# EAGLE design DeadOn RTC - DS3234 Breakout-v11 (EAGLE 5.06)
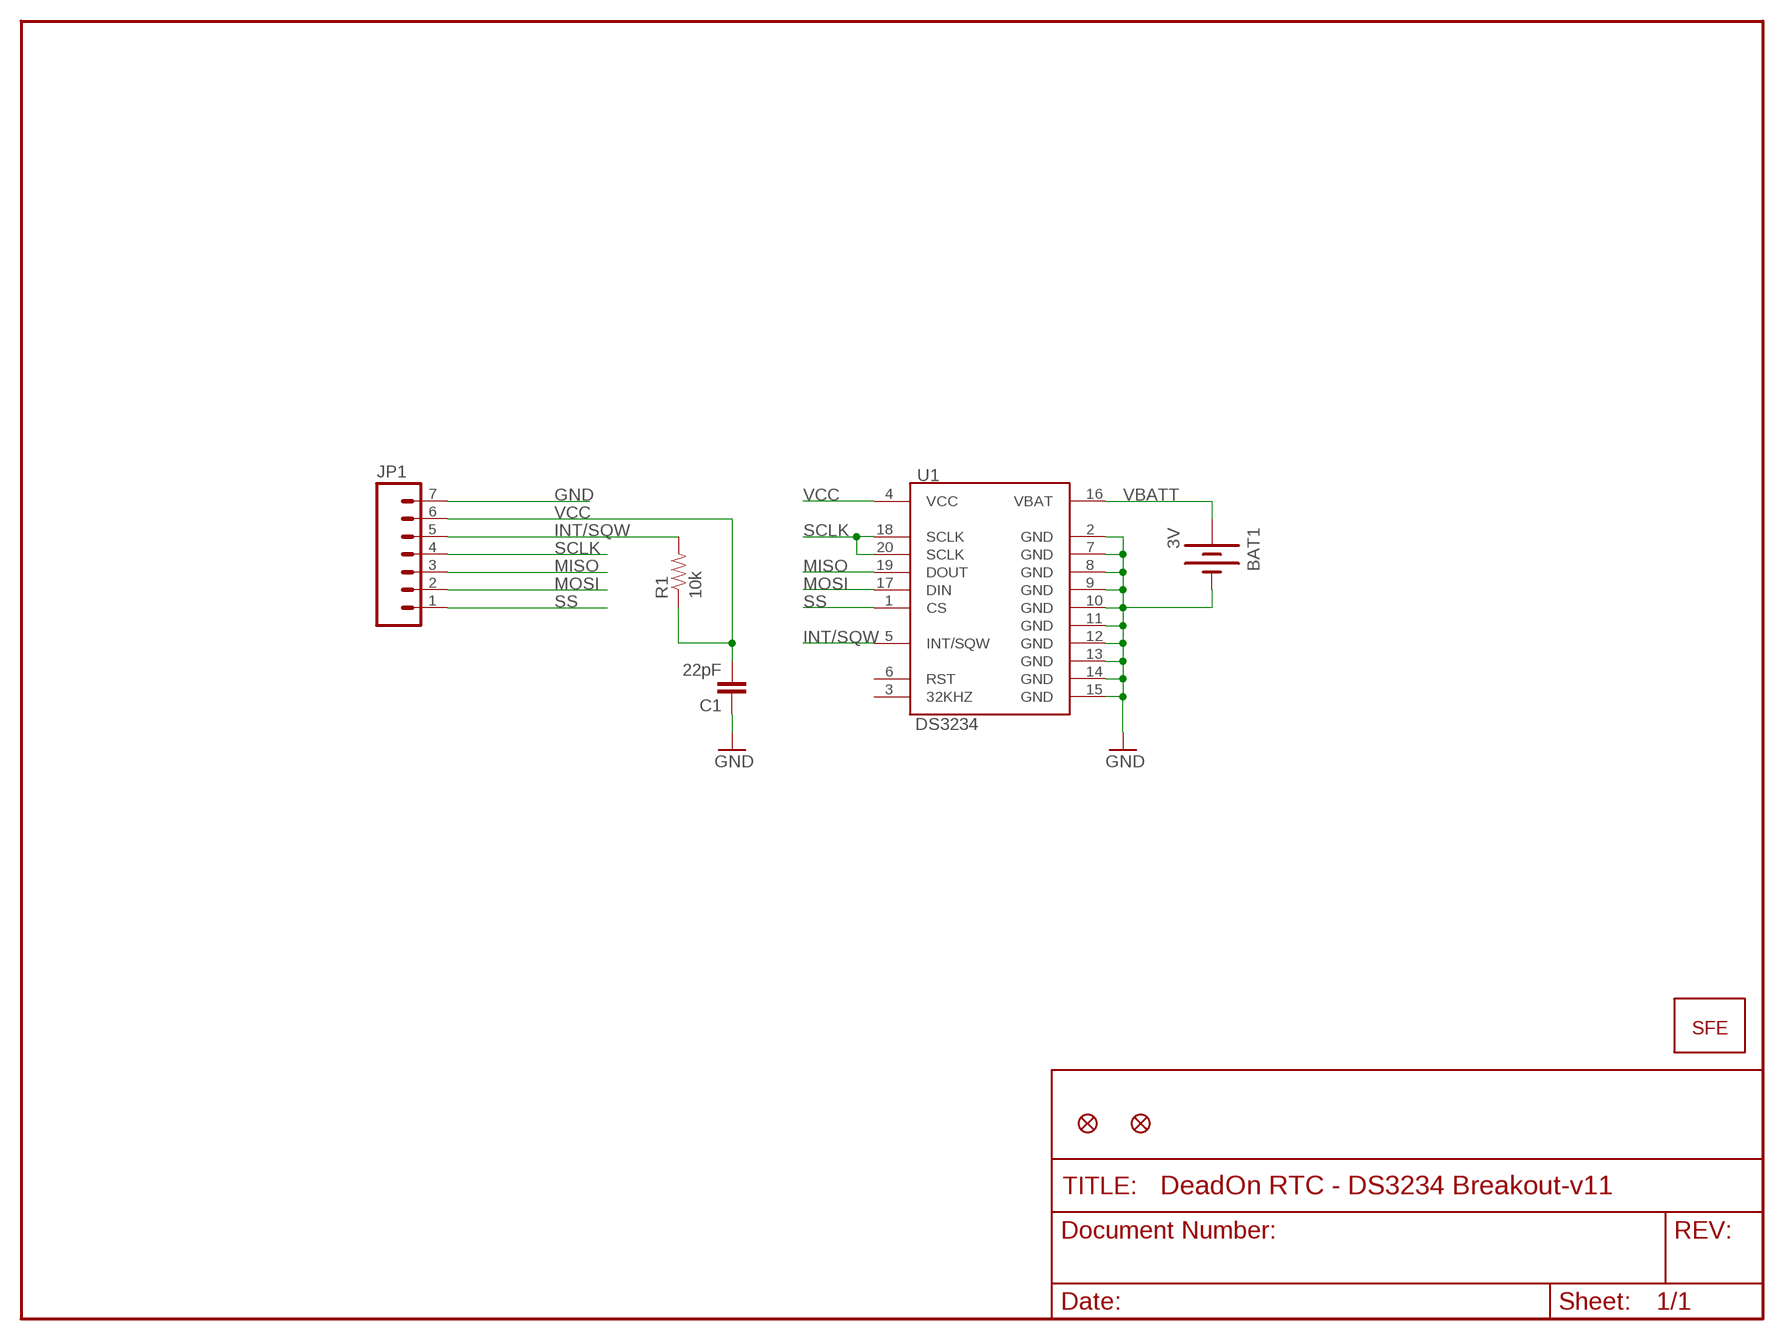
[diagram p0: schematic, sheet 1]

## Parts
BAT1  3V  BATTERY  [BATTCON_12MM_CURVED]
C1  22pF  CAP0402-CAP  [0402-CAP]
JP1  M07  [1X07]
JP2  LOGO-SFESK  [SFE-LOGO-FLAME]
JP3  FIDUCIAL1X2  [FIDUCIAL-1X2]
JP4  FIDUCIAL1X2  [FIDUCIAL-1X2]
R1  10k  RESISTOR0402-RES  [0402-RES]
U1  DS3234  [DS3234]

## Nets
GND: BAT1.GND(-) C1.1 JP1.7 U1.2(GND) U1.7(GND) U1.8(GND) U1.9(GND) U1.10(GND) U1.11(GND) U1.12(GND) U1.13(GND) U1.14(GND) U1.15(GND)
INT/SQW: JP1.5 R1.2 U1.5(INT/SQW)
MISO: JP1.3 U1.19(DOUT)
MOSI: JP1.2 U1.17(DIN)
SCLK: JP1.4 U1.18(SCLK) U1.20(SCLK)
SS: JP1.1 U1.1(CS)
VBATT: BAT1.PWR@1(+) U1.16(VBAT)
VCC: C1.2 JP1.6 R1.1 U1.4(VCC)
Unconnected: U1.3(32KHZ) U1.6(RST)

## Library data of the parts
BAT1 = SparkFun:BATTERY: Battery Holders
C1 = SparkFun:CAP: Capacitor
JP1 = SparkFun:M07: Header 7 Standard 7-pin 0.1" header. Use with straight break away headers (SKU : PRT-00116), right angle break away headers (PRT-00553), swiss pins (PRT-00743), machine pins (PRT-00117), and female headers (PRT-00115). NOTES ON THE VARIANTS LOCK and LOCK_LONGPADS... This footprint was designed to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
JP2 = SparkFun:LOGO-SFE: Spark Fun Electronics PCB Logo
JP3 JP4 = SparkFun:FIDUCIAL: Fiducial Alignment Points
R1 = SparkFun:RESISTOR: Resistor
U1 = SparkFun:DS3234: DS3234 Real Time Clock

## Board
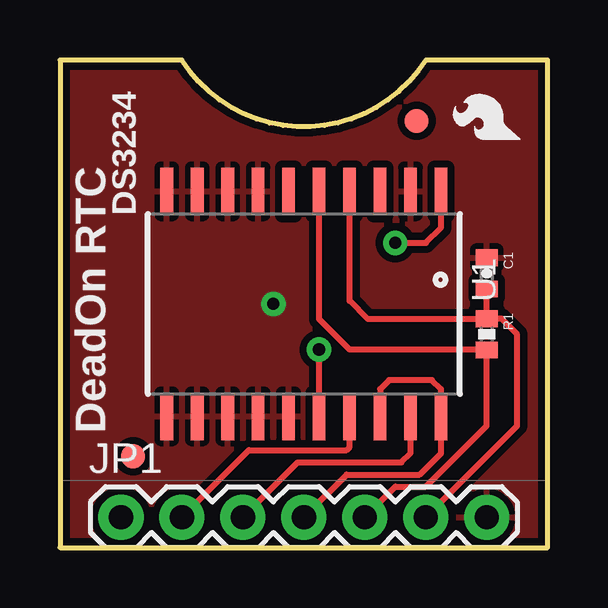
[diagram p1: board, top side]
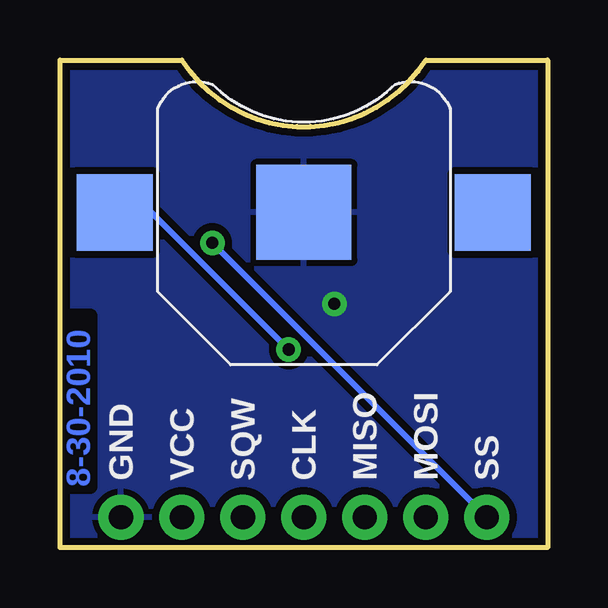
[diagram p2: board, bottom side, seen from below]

Size 20.32 x 20.32 mm. Coordinates in mm from the lower left corner, seen from the top.
Outline: 0,0 20.32,0 20.32,20.32 15.24,20.32 arc-115 5.08,20.32 0,20.32 0,0
Copper layers (1*16): Top 0.035mm / dielectric 1.5mm / Bottom 0.035mm
Design rules "SparkFun": minimum track width 8mil, minimum drill 20mil, track to track 8mil, track to pad 8mil, pad to pad 8mil, via to via 8mil, smd to smd 8mil, copper to edge 8mil, drill to drill 8mil, minimum pad ring 12mil, minimum via ring 10mil, stop-mask expansion 4mil, vias tented up to drill 20mil, thermal gap 10mil

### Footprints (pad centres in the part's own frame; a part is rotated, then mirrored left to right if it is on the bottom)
BATTCON_12MM_CURVED = smd 3.962 x 3.962: GND 0,0 | smd 3.175 x 3.175: PWR@1 -7.874,0; PWR@2 7.874,0
0402-CAP = smd 0.7 x 0.9: 1 -0.65,0; 2 0.65,0
1X07 = drill 1.016 pad 1.88 round: 1 0,0; 2 2.54,0; 3 5.08,0; 4 7.62,0; 5 10.16,0; 6 12.7,0; 7 15.24,0
FIDUCIAL-1X2 = smd 1 x 1: 1 0,0
0402-RES = smd 0.7 x 0.9: 1 -0.65,0; 2 0.65,0
DS3234 = smd 0.53 x 1.98: 1 -5.715,-4.685; 2 -4.445,-4.685; 3 -3.175,-4.685; 4 -1.905,-4.685; 5 -0.635,-4.685; 6 0.635,-4.685; 7 1.905,-4.685; 8 3.175,-4.685; 9 4.445,-4.685; 10 5.715,-4.685; 11 5.715,4.685; 12 4.445,4.685; 13 3.175,4.685; 14 1.905,4.685; 15 0.635,4.685; 16 -0.635,4.685; 17 -1.905,4.685; 18 -3.175,4.685; 19 -4.445,4.685; 20 -5.715,4.685

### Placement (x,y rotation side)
BAT1  10.16,13.97 0 bottom
C1  17.78,11.43 270 top
JP1  2.54,1.27 0 top
JP2  19.18,17.02 90 top
JP3  3.05,3.81 0 top
JP4  14.86,17.78 0 top
R1  17.78,8.89 270 top
U1  10.16,10.16 180 top
U2  CREATIVE_COMMONS  [CREATIVE_COMMONS]  not placed on the board

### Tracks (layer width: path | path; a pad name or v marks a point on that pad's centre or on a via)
GND  (via drill 0.51)
  other vias: 8.89,10.16
  pour Bottom (isolate 0.305): 0,20.32 0,0 20.32,0 20.32,20.32
  pour Top (isolate 0.305): 0,20.32 20.32,20.32 20.32,0 0,0
INT/SQW
  Top 0.254: JP1.5 13.97,2.54 15.24,2.54 17.78,5.08 R1.2 17.77,8.26 12.06,8.26 10.79,9.53 U1.5
MISO
  Top 0.254: U1.19 14.61,3.94 14.22,3.56 9.91,3.56 JP1.3
MOSI
  Top 0.254: U1.17 12.06,4.19 11.94,4.06 7.87,4.06 JP1.2
SCLK
  Top 0.254: U1.18 13.34,6.6 13.72,6.99 15.49,6.99 15.88,6.6 U1.20 15.88,3.94 14.99,3.05 11.94,3.05 JP1.4
SS  (via drill 0.51)
  Top 0.254: v13.97,12.7 15.24,12.7 15.88,13.34 U1.1
  Bottom 0.254: JP1.1 v13.97,12.7
VBATT  (via drill 0.51)
  Top 0.254: U1.16 v10.79,8.26
  Bottom 0.254: BAT1.PWR@1 16.51,13.97 v10.79,8.26
VCC
  Top 0.254: R1.1 C1.2 | R1.1 18.4,9.54 19.05,8.89 19.05,5.08 JP1.6 | U1.4 12.06,10.29 12.83,9.53 17.77,9.53 R1.1

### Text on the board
Bottom: 8-30-2010
tPlace: DeadOn RTC | DS3234
bPlace: SS | MOSI | MISO | CLK | SQW | VCC | GND
bNames: Hilary Hoops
